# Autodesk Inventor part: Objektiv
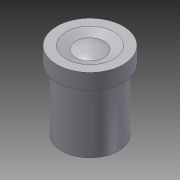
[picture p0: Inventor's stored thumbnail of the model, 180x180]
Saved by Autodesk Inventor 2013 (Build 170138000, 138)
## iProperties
Created: 2012-10
Part Number: Objektiv
Material: Aluminium 6061
Document SubType Name: Modeling
Designer: rYan
Density: 2.71 g/cm^3
Mass: 5.24813 g
Surface Area: 9.57222 cm^2
Volume: 1.93658 cm^3
Author: rYan
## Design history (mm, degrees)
sketch "Skizze5"
  geometry: L1 (-8.47, 0)-(1.821, 0) reference; L2 (-3, 0)-(-6, 0); L3 (-6, 0)-(-6, 13); L4 (-6, 13)-(-7, 13); L5 (-7, 13)-(-7, 16.3); L6 (-7, 16.3)-(-5, 16.3); L7 (-5, 16.3)-(-3, 15.572); L8 (-3, 0)-(-3, 0.5); L9 (-3, 0.5)-(0, 0.5); L10 (0, -3.289)-(0, 19.735) reference; L11 (0, 16.3)-(0, 0.5); A1 r 8 centre (0.351, 8.308) between (0, 16.3) and (-3, 15.572); 1 further point
  constraints: 18 end point, 3 parallel, 3 perpendicular, 2 point on circle, 2 point on line, 1 centre point, 1 collinear
  dimensions: "d12" = 6 distance of point (0, 0) L2.end; "d13" = 13 distance of L2.end L3.end; "d14" = 1 distance of L3.end L4.end; "d15" = 3.3 distance of L4.end L5.end; "d16" = 2 distance of L5.end L6.end; "d17" = 160 deg angle of L6 L7; "d18" = 2 horizontal distance of L7.end L6.end; "d19" = 8 radius of A1; "d23" = 0.5 distance of L2.start L8.end; "d24" = 3 distance of L8.end L9.end
revolve "Umdrehung1" sketch "Skizze5" stored, may be unused: angle "d20" = 90 deg
node "Volumenkörper2"
